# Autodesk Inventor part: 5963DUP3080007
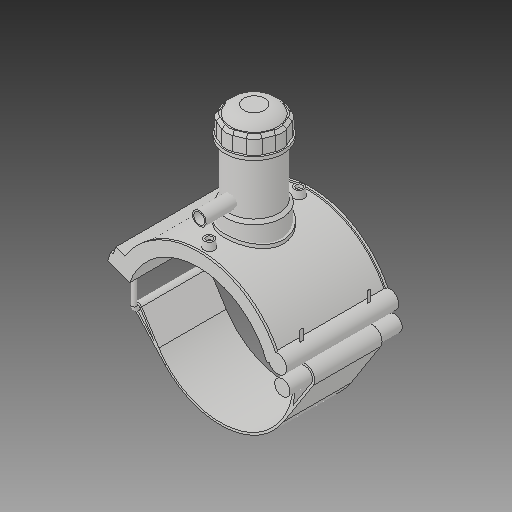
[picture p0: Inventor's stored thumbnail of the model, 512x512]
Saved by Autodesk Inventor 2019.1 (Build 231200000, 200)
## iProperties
Created: 2017-07
Part Number: 5963DUP3080007
Material: Generic
Description: PLASSON TAPPING SADDLE 8''DIPS x 3/4''CTS
Document SubType Name: Modeling
Designer: KIM
Density: 1 g/cm^3
Appearance: Default
Author: KIM
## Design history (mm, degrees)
derived "5963DBP_5963BUP.ipt"
feature "Solid1::5963DBP_5963BUP.ipt"
feature "Solid2::5963DBP_5963BUP.ipt"
feature "Solid3::5963DBP_5963BUP.ipt"
tag "TaggingFeature1"
body "Solid1"
body "Solid2"
body "Solid3"
other parameters: "d0" = 228.9, "d2" = 269.748, "d3" = 57.225, "d4" = 176.022, "d5" = 0, "d6" = 0.1, "d8" = 0, "d19" = 6, "d20" = 6, "d21" = 105.6132, "d23" = 0, "d24" = 52.8066, "d26" = 0, "d27" = 3, "d28" = 3, "d29" = 3, "d30" = 76.3, "d31" = 6, "d32" = 0, "d33" = 0, "d34" = 0.6, "d40" = 138.07248, "d41" = 91.56, "d43" = 0, "d45" = 0, "d47" = 238.3752, "d70" = 15, "d72" = 0, "d73" = 6, "d75" = 5, "d76" = 0, "d77" = 11.445, "d78" = 144.45, "d79" = 15, "d80" = 70.4088, "d82" = 5 deg, "d84" = 4, "d85" = 14, "d86" = 0, "d87" = 3, "d88" = 0, "d89" = 1, "d90" = 1, "d91" = 140.8176, "d92" = 0, "d93" = 0.5, "d94" = 120.47368, "d96" = 270.83448, "d97" = 3.52044, "d98" = 0, "d120" = 140 deg, "d121" = 24.228, "d122" = 20 deg, "d123" = 531.048, "d124" = 159.3144, "d126" = 0, "d143" = 235.767, "d145" = 28.17231, "d149" = 3.4335, "d150" = 30.98954, "d153" = 176.022, "d154" = 0, "d156" = 132.762, "d157" = 160 deg, "d159" = 7.3248, "d161" = 3.4335, "d162" = 105.6132, "d163" = 0, "d164" = 114.45, "d167" = 22.89, "d168" = 129.5239, "d170" = 3.4335, "d172" = 0, "d173" = 1, "d175" = 114.45, "d176" = 20 deg, "d177" = 16.023, "d178" = 36.624, "d180" = 0, "d183" = 14.6496, "d184" = 12.8184, "d185" = 57.20715, "d186" = 57.20715, "d187" = 132.762, "d188" = 10.9872, "d189" = 16.023, "d190" = 0, "d191" = 199.143, "d193" = 7.3248, "d194" = 6.16077, "d195" = 90 deg, "d197" = 0, "d199" = 0, "d200" = 18.312, "d202" = 0, "d203" = 177.038, "d204" = 86.982, "d205" = 64.092, "d206" = 77.826, "d207" = 132.7785, "d208" = 138.08964, "d209" = 164.64534, "d210" = 78.7416, "d211" = 91.56, "d212" = 73.248, "d213" = 48.5766, "d216" = 0, "d217" = 22.89, "d218" = 22.89, "d219" = 4.578, "d222" = 228.9, "d224" = 0, "d225" = 65.024, "d226" = 22.1, "d227" = 17.68, "d228" = 86.106, "d230" = 4.578, "d_" = 228.9, "B_" = 179.832, "L_" = 176.022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
